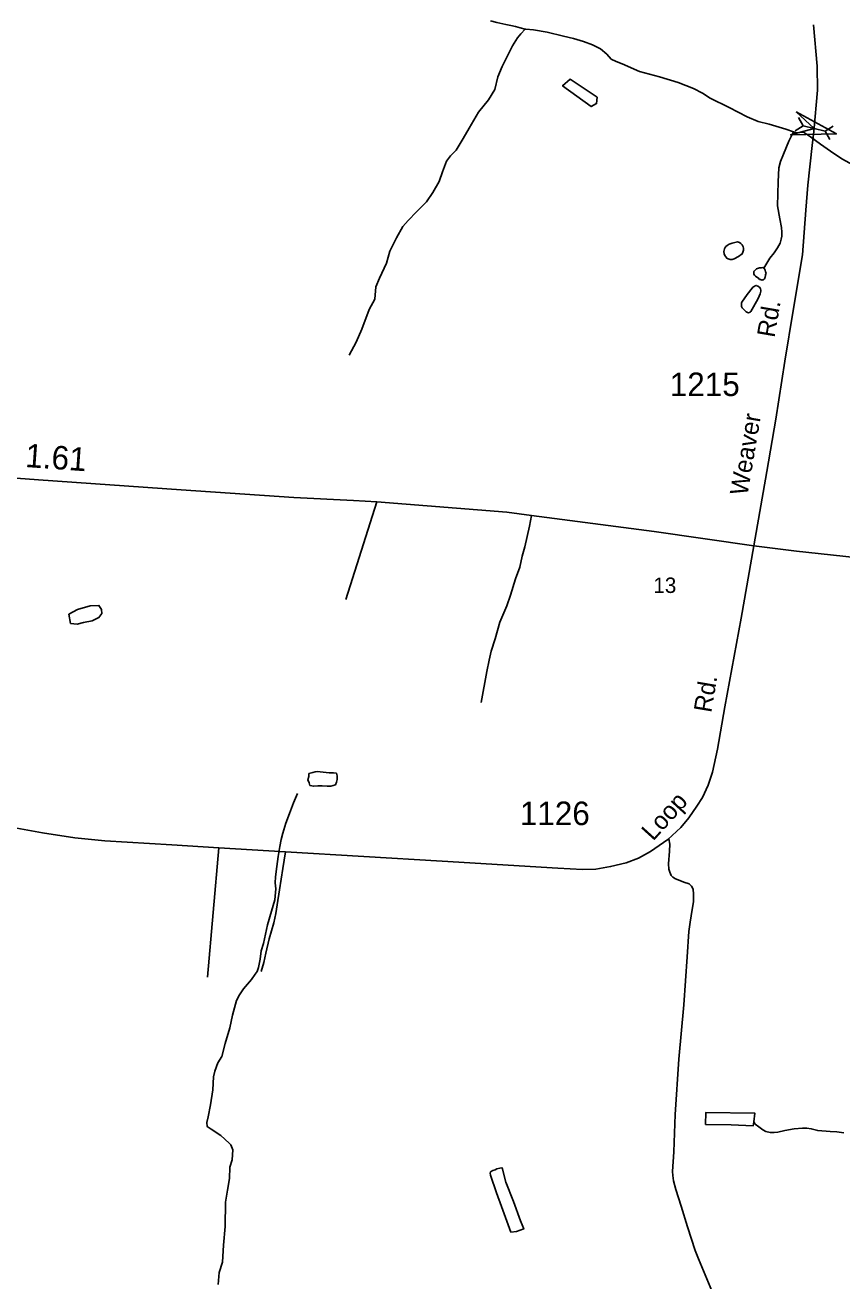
# Model space of a CAD drawing. Extents: x 2206922 to 2357709, y 510027 to 673830.
# Drawn here: x 2255208 to 2259549, y 558977 to 565653 of the extents above; entities that cross this region are included whole.
import ezdxf

# ---------------------------------------------------------------- set-up
doc = ezdxf.new("R2010")
doc.units = 0
for name, color, linetype in [('Exist Hydrographic Creek Single Shore', 7, 'Continuous'), ('Exist Hydrographic Misc Water Feature', 7, 'Continuous'), ('Exist Road Non-System Type 51', 7, 'Continuous'), ('Exist Road Primary US Attributed', 7, 'Continuous'), ('Exist Road Primary US Label', 7, 'Continuous'), ('Exist Road Primary US Mileage Hundredths English Label', 7, 'Continuous'), ('Exist Road Secondary Structure Pipe CELL', 7, 'Continuous'), ('Exist Road Secondary Structure Standard Bridge Attributed CELL', 7, 'Continuous'), ('Exist Road Secondary Type 51 Attributed', 7, 'Continuous'), ('Exist Road Secondary Type 51 Label', 7, 'Continuous'), ('Exist Road Secondary Type 51 Number Label', 7, 'Continuous')]:
    doc.layers.add(name, color=color, linetype=linetype)

msp = doc.modelspace()

# ---------------------------------------------------------------- linework, layer by layer
at = {"layer": 'Exist Hydrographic Creek Single Shore'}
for points in [[(2257681.3, 565674.7), (2257715.7, 565667.1), (2257763.5, 565655.4), (2257789.7, 565649.8), (2257813.7, 565645.8), (2257839.8, 565638.2), (2257865.6, 565630.3)], [(2257865.6, 565630.3), (2257869.9, 565630.4), (2257910.1, 565626.8), (2257982.1, 565615.2), (2258070, 565593.8), (2258122.5, 565582.2), (2258176.1, 565564.8), (2258224.2, 565547.4), (2258266.5, 565525.6), (2258298.9, 565498.1), (2258323.1, 565472.1), (2258348.7, 565458.5), (2258380.9, 565446.8), (2258473.4, 565405.2), (2258579.4, 565378.3), (2258679.7, 565347), (2258759.8, 565315.8), (2258808.2, 565290.3), (2258848.2, 565264.4), (2258950.5, 565215.3), (2259044.9, 565164.2), (2259103.5, 565140.8), (2259163.4, 565125.2), (2259251.3, 565099.8), (2259291.5, 565086)], [(2259291.5, 565086), (2259307.7, 565080.4), (2259345.5, 565082.8), (2259382, 565059.1), (2259436.1, 565019.3), (2259488, 564981.8), (2259548.7, 564942.3), (2259590.7, 564918.9), (2259640.9, 564897.1), (2259745.5, 564856.2), (2259843.7, 564822.8), (2259919.6, 564801.6)]]:
    msp.add_lwpolyline(points, dxfattribs=at)
at = {"layer": 'Exist Hydrographic Misc Water Feature'}
for points in [[(2256930.8, 563897.7), (2256967.9, 563968), (2256997, 564036.2), (2257036.6, 564140.5), (2257065.9, 564196.5), (2257071.4, 564260.5), (2257090.9, 564306.7), (2257128.6, 564386.9), (2257145.7, 564450.9), (2257181.1, 564521.4), (2257215, 564581.5), (2257244.5, 564613.6), (2257288, 564660.2), (2257341.7, 564712.5), (2257375.1, 564762.6), (2257408.7, 564820.8), (2257426.4, 564873.3), (2257447.5, 564929.3), (2257469.2, 564957.7), (2257499.4, 564987.6), (2257536.5, 565050.1), (2257568.1, 565104.2), (2257617.3, 565190.4), (2257671, 565254.9), (2257704.4, 565311.1), (2257720.2, 565377.2), (2257743.6, 565433.3), (2257781.1, 565507.6), (2257798.6, 565541.8), (2257824.2, 565585.8), (2257842, 565606.2), (2257865.6, 565630.3)], [(2258248.4, 565269.6), (2258105.7, 565364.5), (2258064.3, 565330.2), (2258217.1, 565219.2), (2258245, 565235.7), (2258248.4, 565269.6)], [(2259133.4, 564361.3), (2259166.9, 564413.4), (2259189, 564441.7), (2259206.8, 564467.8), (2259220.6, 564493.7), (2259226.5, 564513.9), (2259230, 564530), (2259229.8, 564552), (2259228, 564576.2), (2259219.4, 564622), (2259206.8, 564691.7), (2259208.1, 564755.6), (2259209.9, 564819.8), (2259213.2, 564893.9), (2259223, 564927.7), (2259238.4, 564965.9), (2259266.3, 565035.9), (2259291.5, 565086)], [(2258938.8, 564481.8), (2258950.5, 564487.8), (2258966.5, 564493.9), (2258980.3, 564497.9), (2258994.2, 564500.3), (2259004.7, 564496.3), (2259012.5, 564492.2), (2259018.8, 564484.4), (2259024.8, 564474.2), (2259026.8, 564466.1), (2259027, 564456.4), (2259022.7, 564446.5), (2259019, 564436.5), (2258999.1, 564422.1), (2258977.2, 564410), (2258965.5, 564406.1), (2258955.3, 564406), (2258945.2, 564410), (2258937.4, 564413.5), (2258927, 564427.7), (2258923.1, 564437.6), (2258920.8, 564449.7), (2258924.9, 564463.7), (2258928.8, 564469.6), (2258932.7, 564475.5), (2258938.8, 564481.8)], [(2259133.4, 564361.3), (2259137.5, 564357.4), (2259141.6, 564349.5), (2259143.9, 564341.5), (2259145.9, 564333.5), (2259143.7, 564325.3), (2259143.9, 564321.6), (2259142.1, 564313.3), (2259140.2, 564309.6), (2259138, 564303.4), (2259132.2, 564299.4), (2259128.3, 564299.2), (2259124.2, 564297.4), (2259120.1, 564299.2), (2259115.8, 564301.1), (2259112.1, 564301.2), (2259108, 564305.1), (2259090, 564318.8), (2259084.2, 564322.9), (2259081.8, 564328.9), (2259081.6, 564333), (2259081.8, 564337), (2259081.6, 564342.8), (2259084, 564346.9), (2259089.8, 564350.9), (2259095.3, 564356.9), (2259101.2, 564359.3), (2259111.7, 564363), (2259121.5, 564363.1), (2259129.5, 564363.5), (2259133.4, 564361.3)], [(2259019.4, 564150.6), (2259015.3, 564156.5), (2259015.3, 564162.5), (2259015.3, 564166.6), (2259015.3, 564172.3), (2259014.7, 564176.4), (2259017.2, 564180.5), (2259045.1, 564220.5), (2259072.5, 564254.9), (2259076.4, 564258.8), (2259082.8, 564263.1), (2259088.5, 564267.1), (2259094.3, 564269), (2259102.3, 564265), (2259110.5, 564259.3), (2259114.6, 564255), (2259116.4, 564251.1), (2259118.5, 564243.1), (2259118.5, 564237.5), (2259114.8, 564223.4), (2259104.9, 564199.3), (2259079.1, 564154.9), (2259065.4, 564131.1), (2259061.3, 564126.8), (2259053.5, 564122.7), (2259047.3, 564124.9), (2259043.4, 564126.7), (2259039.5, 564128.5), (2259027.4, 564140.4), (2259019.4, 564150.6)], [(2255440.5, 562522.2), (2255486.2, 562546.5), (2255554.1, 562565.1), (2255599.8, 562567.5), (2255613.9, 562545.5), (2255616.2, 562525.7), (2255600.2, 562503.4), (2255564.9, 562485.2), (2255518.8, 562476.7), (2255484.7, 562468.5), (2255449.3, 562472.2), (2255440.5, 562522.2)], [(2256716.5, 561674.9), (2256736.8, 561679.2), (2256748.7, 561683.5), (2256760.8, 561685.3), (2256824.6, 561678.1), (2256846.7, 561678), (2256862.5, 561676), (2256866.6, 561662.4), (2256867.2, 561642.1), (2256863.1, 561628.1), (2256857.4, 561614), (2256845.3, 561610.1), (2256833.4, 561607.8), (2256813.3, 561607.6), (2256787.2, 561609.5), (2256763, 561609.5), (2256741.5, 561607.1), (2256731.1, 561609.1), (2256721.2, 561610.9), (2256717.1, 561624.9), (2256711, 561640.9), (2256714.9, 561659), (2256716.5, 561674.9)], [(2256656, 561568.5), (2256634.1, 561518.3), (2256612.3, 561462.3), (2256593.1, 561410.1), (2256577.5, 561358.1), (2256568, 561323.8), (2256562.1, 561285.8), (2256552.7, 561233.7), (2256546.5, 561179.9), (2256539.3, 561125.8), (2256537.3, 561093.7), (2256539.7, 561061.7), (2256534.2, 561003.7), (2256516.8, 560941.9), (2256495.4, 560869.6), (2256474.3, 560771.5), (2256462.6, 560731.4), (2256456.9, 560687.3), (2256449.1, 560643.5), (2256441.7, 560621.5), (2256431.3, 560607.2), (2256411.8, 560578.9), (2256368.3, 560530.7), (2256346.6, 560498.7), (2256330.8, 560468.3), (2256309.3, 560390.4), (2256295.9, 560322.3), (2256270.7, 560240.1), (2256253.5, 560170.1), (2256231.5, 560135.7), (2256215.8, 560091.8), (2256208.2, 560061.8), (2256204.7, 559993.8), (2256193.4, 559913.6), (2256180.1, 559849.4), (2256174.3, 559819.5), (2256176.2, 559797.7), (2256196.5, 559783.7), (2256248.6, 559750.3), (2256293.1, 559708.7), (2256301.1, 559700.6), (2256311.3, 559674.8), (2256307.8, 559621), (2256295.9, 559582.6), (2256294.5, 559520.8), (2256282.8, 559460.5), (2256273.6, 559396.6), (2256270.5, 559266.5), (2256261.5, 559166.5), (2256256.4, 559076.4), (2256238.7, 559022.3), (2256233.2, 558958.2)], [(2259080.5, 559823.4), (2259076.8, 559801.3), (2258960.8, 559806.2), (2258824.8, 559809.3), (2258826.1, 559873.1), (2259086.1, 559869.2), (2259080.5, 559823.4)], [(2259080.5, 559823.4), (2259088.7, 559811.3), (2259107, 559795.5), (2259128.9, 559779.6), (2259145.1, 559771.9), (2259167.1, 559766.2), (2259189.2, 559766.1), (2259209.1, 559768.4), (2259245, 559776.8), (2259294.8, 559785.1), (2259340.5, 559789.5), (2259362.7, 559789.4), (2259386.7, 559785.8), (2259420.7, 559776.2), (2259486.5, 559770.7), (2259522.8, 559768.9), (2259558.7, 559765.1)], [(2257681.3, 559557.9), (2257693.4, 559564.2), (2257705.5, 559568), (2257715.5, 559572.2), (2257731.1, 559576.3), (2257743.4, 559578.5), (2257762.3, 559502.7), (2257802.9, 559399.3), (2257841.6, 559297.3), (2257858, 559253.5), (2257819.9, 559239.3), (2257789.7, 559237), (2257739.3, 559372.3), (2257712.4, 559446.1), (2257681.7, 559540), (2257679.6, 559550), (2257681.3, 559557.9)]]:
    msp.add_lwpolyline(points, dxfattribs=at)
at = {"layer": 'Exist Road Non-System Type 51'}
for p, q in [((2256911.8, 562599.7), (2257076.5, 563118.4)), ((2256176.5, 560592.7), (2256237.6, 561280))]:
    msp.add_line(p, q, dxfattribs=at)
for points in [[(2257631.2, 562052.5), (2257661.6, 562216.7), (2257673.8, 562277.5), (2257684.4, 562324.7), (2257705.7, 562390), (2257731.5, 562478.2), (2257768, 562564.9), (2257787.8, 562622.7), (2257813.6, 562709.4), (2257837.9, 562771.7), (2257850.1, 562829.5), (2257863.7, 562879.7), (2257888.1, 562989.2), (2257898.7, 563045.4)], [(2258629.3, 561327.5), (2258635.2, 561299.3), (2258632.3, 561262.2), (2258627.8, 561194), (2258629.3, 561165.8), (2258633.8, 561149.5), (2258641.2, 561131.7), (2258650.1, 561124.3), (2258664.9, 561115.4), (2258687.1, 561106.5), (2258709.3, 561097.6), (2258737.5, 561088.7), (2258749.3, 561075.4), (2258758.2, 561059.1), (2258759.7, 561032.4), (2258759.7, 560992.4), (2258753.8, 560952.3), (2258743.4, 560884.1), (2258736, 560835.2), (2258727.1, 560700.3), (2258709.3, 560445.2), (2258682.7, 560156.1), (2258663.4, 559861), (2258656, 559663.8), (2258648.6, 559558.6), (2258650.1, 559537.8), (2258654.5, 559509.6), (2258666.4, 559463.7), (2258694.5, 559374.7), (2258728.6, 559265), (2258770.1, 559139), (2258786.4, 559094.5), (2258857.5, 558924)], [(2256591.4, 561258.8), (2256578.4, 561168.8), (2256559.1, 561056.1), (2256547.2, 560976.1), (2256539.8, 560930.1), (2256529.4, 560881.2), (2256504.3, 560795.2), (2256488, 560719.5), (2256476.1, 560670.6), (2256462.8, 560621.7)]]:
    msp.add_lwpolyline(points, dxfattribs=at)
at = {"layer": 'Exist Road Primary US Attributed'}
for points in [[(2250642, 563984.6), (2250959.8, 563926.6), (2251383.8, 563844.3), (2251792.7, 563765.1), (2252297.3, 563672.7), (2252692, 563603.4), (2253077.8, 563530.8), (2253486.3, 563457.5), (2253741.8, 563406.5), (2254163.1, 563331.3), (2254258.8, 563314.6), (2254351.5, 563300.9), (2254416.9, 563293.3), (2254778.6, 563273.5), (2255279.3, 563236.1), (2256037.4, 563182.4), (2256635.4, 563141.3), (2256953.4, 563126), (2257076.5, 563118.4), (2257768, 563063.7), (2257898.7, 563045.4), (2258552.2, 562960.3), (2259081.1, 562884.2)], [(2259081.1, 562884.2), (2259308, 562855.9), (2259684.8, 562816.1), (2260094.7, 562781.6), (2260665, 562734.1), (2261027, 562707.2), (2261177, 562692.4), (2261692, 562653.9), (2262606.2, 562584.4), (2263513, 562497.3)]]:
    msp.add_lwpolyline(points, dxfattribs=at)
at = {"layer": 'Exist Road Secondary Structure Pipe CELL'}
for p, q in [((2259300, 565090.9), (2259342.9, 565118)), ((2259318.2, 565162.3), (2259342.9, 565118)), ((2259342.9, 565118), (2259460.2, 565088.2)), ((2259503.1, 565115.4), (2259460.2, 565088.2)), ((2259484.9, 565043.9), (2259460.2, 565088.2))]:
    msp.add_line(p, q, dxfattribs=at)
at = {"layer": 'Exist Road Secondary Structure Standard Bridge Attributed CELL'}
msp.add_lwpolyline([(2259306, 565191.2), (2259520.1, 565074.5), (2259276.3, 565068.5), (2259401.6, 565103.1)], close=True, dxfattribs=at)
at = {"layer": 'Exist Road Secondary Type 51 Attributed'}
for points in [[(2259398.7, 565653.3), (2259418.5, 565434.3), (2259420, 565306.6), (2259400.2, 565087.6), (2259391.5, 565013.3)], [(2259391.5, 565013.3), (2259368.3, 564801.8), (2259357.7, 564669.5), (2259339.5, 564432.2), (2259290.8, 564135.7), (2259245.2, 563866.6), (2259198.1, 563557.9), (2259149.5, 563279.6), (2259081.1, 562884.2)], [(2255144.2, 561387.1), (2255300.6, 561359.2), (2255471.6, 561331.7), (2255631.2, 561316.5), (2255986.8, 561295.2), (2256237.6, 561280), (2256591.4, 561258.8), (2257424.5, 561208.5), (2258040, 561172), (2258170.7, 561164.4), (2258240.6, 561165.9), (2258319.7, 561179.6), (2258403.3, 561199.4), (2258468.6, 561225.2), (2258532.4, 561260.2), (2258624.7, 561323.8), (2258693.3, 561388.2), (2258736.1, 561438.1), (2258778.7, 561500.5), (2258807.5, 561547.6), (2258837.9, 561613), (2258862.2, 561681.4), (2258888.1, 561804.6), (2258927.6, 562029.7), (2259014.2, 562499.5), (2259081.1, 562884.2)]]:
    msp.add_lwpolyline(points, dxfattribs=at)

# ---------------------------------------------------------------- texts
at = {"layer": 'Exist Road Primary US Label'}
msp.add_text('13', height=82.02, dxfattribs=at).set_placement((2258546.9, 562634.1))
at = {"layer": 'Exist Road Primary US Mileage Hundredths English Label'}
msp.add_text('1.61', height=125, rotation=355.94841, dxfattribs=at).set_placement((2255205.6, 563303.9))
at = {"layer": 'Exist Road Secondary Type 51 Label'}
for s, rotation, p in [('Rd.', 80.23769, (2259190.6, 563988.1)), ('Weaver', 80.37669, (2259046.7, 563148.1)), ('Rd.', 80.38491, (2258854.5, 561994.4)), ('Loop', 47.91147, (2258545.6, 561311.8))]:
    msp.add_text(s, height=95, rotation=rotation, dxfattribs=at).set_placement(p)
at = {"layer": 'Exist Road Secondary Type 51 Number Label'}
for s, p in [('1215', (2258634.4, 563680.8)), ('1126', (2257837.3, 561400.2))]:
    msp.add_text(s, height=125, dxfattribs=at).set_placement(p)

doc.saveas('drawing.dxf')
